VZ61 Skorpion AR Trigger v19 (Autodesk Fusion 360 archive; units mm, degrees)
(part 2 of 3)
extrude "Extrude35" cut sketch "Sketch22" profile of C1 against normal blind 9.398
extrude "Extrude36" cut of existing geometry blind 12
extrude "Extrude37" cut of existing geometry blind -88.9
extrude "Extrude38" add of existing geometry blind 0.0762 bodies "Body1", "Body2", "Body3", "Body4", "Body5"
chamfer "Chamfer2" distance 0.762
extrude "Extrude39" cut sketch "Sketch22" profile of C1 along normal blind 3
delete_face "DeleteFace1"
extrude "Extrude40" cut sketch "Sketch21" profile of L15 C2 L16 L17 L18 L19 L20 L21 L22 along normal blind 9.398
extrude "Extrude41" add of existing geometry blind 82.55
extrude "Extrude42" add of existing geometry blind 0.635
extrude "Extrude43" add of existing geometry blind 0.0254
external_derived "ExternalDerived2" bodies "Body5"
move "Move1"
move "Move2"
sketch "Sketch23" plane through (0, 65.024, 0) normal (0, -1, 0) x axis (1, 0, 0)
  line L1 (10.524, -2.2659) -> (15.9105, -2.2659)
  line L2 (17.4496, 2.7362) -> (14.383, 2.7362)
  line L3 (17.78, 3.81) -> (17.4496, 2.7362)
  line L4 (17.78, 10.16) -> (17.78, 3.81)
  line L5 (12.7, 25.4) -> (17.78, 10.16)
  line L6 (-12.7, 25.4) -> (12.7, 25.4)
  line L7 (-17.78, 10.16) -> (-12.7, 25.4)
  line L8 (-17.78, 3.81) -> (-17.78, 10.16)
  line L9 (-15.3535, -4.0762) -> (-17.78, 3.81)
  line L10 (-12.7, -12.7) -> (-15.3535, -4.0762)
  line L11 (-12.7, -12.6992) -> (-12.7, -12.7)
  line L12 (10.922, -12.6992) -> (-12.7, -12.6992)
  line L13 (10.922, -12.7) -> (10.922, -12.6992)
  line L14 (12.7, -12.7) -> (10.922, -12.7)
  line L15 (15.9105, -2.2659) -> (12.7, -12.7)
  line L16 (-1.2117, 23.5797) -> (-1.2117, 19.8432)
  line L17 (1.2883, 23.5797) -> (-1.2117, 23.5797)
  line L18 (1.2883, 19.8318) -> (1.2883, 23.5797)
  line L19 (14.3832, 25.3967) -> (19.4765, 10.1169)
  line L20 (17.3838, 25.3951) -> (22.4765, 10.1169)
  line L21 (17.3838, 25.3951) -> (14.3832, 25.3967)
  line L22 (0, 33.02) -> (0, 38.1)
  line L23 (-17.3838, 25.3951) -> (-22.4765, 10.1169)
  line L24 (-17.3838, 25.3951) -> (-14.3832, 25.3967)
  line L25 (-14.3832, 25.3967) -> (-19.4765, 10.1169)
  line L26 (-19.4765, 10.1169) -> (-22.4765, 10.1169)
  line L27 (22.4765, 10.1169) -> (19.4765, 10.1169)
  line L28 (-12.7, 25.4) -> (-14.3832, 25.3967)
  line L29 (-17.78, 10.16) -> (-19.4765, 10.1169)
  line L30 (14.3832, 25.3967) -> (12.7, 25.4)
  line L31 (19.4765, 10.1169) -> (17.78, 10.16)
  arc A1 centre (10, 2.128) radius 4.425 clockwise from (10.524, -2.2659) to (14.383, 2.7362)
  arc A2 centre (0, 11.43) radius 8.5 clockwise from (1.2883, 19.8318) to (-1.2117, 19.8432)
  circle C1 centre (0, 0) radius 2.75
  point P25 (19.4765, 10.1169)
  point P27 (19.4765, 10.1169)
  point P26 (22.4765, 10.1169)
  point P28 (22.4765, 10.1169)
  point P34 (-19.4765, 10.1169)
  point P37 (-22.4765, 10.1169)
  point P33 (-19.4765, 10.1169)
  point P35 (-22.4765, 10.1169)
  point P29 (17.3838, 25.3951)
  point P36 (-17.3838, 25.3951)
  point P30 (14.3832, 25.3967)
  point P38 (-14.3832, 25.3967)
  point P39 (-19.4765, 10.1169)
  point P40 (22.4765, 10.1169)
  point P10 (-12.7, 25.4)
  point P41 (-12.7, 25.4)
  point P42 (-19.4765, 10.1169)
  point P11 (-17.78, 10.16)
  point P43 (-17.78, 10.16)
  point P9 (12.7, 25.4)
  point P44 (12.7, 25.4)
  point P8 (17.78, 10.16)
  point P45 (17.78, 10.16)
  point P46 (19.4765, 10.1169)
  parallel L5 L19
  parallel L19 L20
  coincident P25 P27
  coincident P26 P28
  vertical L22
  symmetric P25 L22 P34
  symmetric P26 L22 P37
  symmetric P27 L22 P33
  symmetric P28 L22 P35
  symmetric P29 L22 P36
  symmetric P30 L22 P38
  coincident P33 P39
  coincident P28 P40
  coincident P10 P41
  coincident P33 P42
  coincident P11 P43
  coincident P9 P44
  coincident P8 P45
  coincident P27 P46
extrude "Extrude44" new body sketch "Sketch23" profile of L19 L20 L21 L23 L24 L25 L26 L27 along normal blind 24.6888
extrude "Extrude45" new body sketch "Sketch23" profile of L5 L7 L19 L20 L21 L23 L24 L25 L26 L27 L28 L29 L30 L31 against normal blind 6.35
sketch "Sketch24" plane through (9.4765, 0, 0) normal (1, 0, 0) x axis (0, 1, 0)
  line L1 (49.0432, -27.3325) -> (58.1554, -27.3325)
  line L2 (49.2242, -28.4751) -> (49.0432, -27.3325)
  line L3 (40.335, -29.8831) -> (49.2242, -28.4751)
  line L4 (41.1172, -34.8215) -> (40.335, -29.8831)
  line L5 (58.8956, -32.0057) -> (41.1172, -34.8215)
  line L6 (58.1554, -27.3325) -> (58.8956, -32.0057)
  line L7 (59.531, -23.368) -> (57.531, -23.368)
  line L8 (65.024, -10.16) -> (59.531, -23.368)
  line L9 (66.802, -12.7) -> (65.024, -10.16)
  line L10 (58.8956, -32.0057) -> (66.802, -12.7)
  line L11 (58.8956, -32.0057) -> (57.531, -23.368)
  point P7 (58.8956, -32.0057)
  point P12 (58.8956, -32.0057)
  point P8 (57.531, -23.368)
  point P9 (59.531, -23.368)
  horizontal L7
  coincident P7 P12
  dimension "d120" distance P8 P9 = 2
extrude "Extrude46" add sketch "Sketch24" profile of L7 L8 L9 L10 L11 against normal blind 18.9992 bodies "Body4", "Body1"
extrude "Extrude47" cut of existing geometry blind 31.75 second side blind 11.43
extrude "Extrude48" add of existing geometry blind 4.699 bodies "Body3"
extrude "Extrude49" add of existing geometry blind 13.0048
extrude "Extrude50" cut of existing geometry blind -7.62
delete_face "DeleteFace2"
delete_face "DeleteFace3"
delete_face "DeleteFace4"
extrude "Extrude51" cut of existing geometry blind -13.97
delete_face "DeleteFace5"
extrude "Extrude52" add of existing geometry blind 13.0048
delete_face "DeleteFace6"
extrude "Extrude53" cut of existing geometry blind -10.16
extrude "Extrude54" cut of existing geometry blind -8.89
delete_face "DeleteFace7"
delete_face "DeleteFace8"
extrude "Extrude55" add of existing geometry blind 0.01 (= "3.937E-04 in")
extrude "Extrude56" add of existing geometry blind 0.01 (= "3.937E-04 in")
extrude "Extrude57" add of existing geometry blind 6.35
extrude "Extrude58" add of existing geometry blind 6.35
sketch "Sketch25" plane through (-17.78, 0, 0) normal (-1, 0, 0) x axis (0, -1, 0)
  line L1 (-193.04, 3.81) -> (-193.04, 10.16)
  line L2 (-65.024, 3.81) -> (-193.04, 3.81)
  line L3 (-65.024, 10.16) -> (-65.024, 3.81)
  line L4 (-71.374, 10.16) -> (-65.024, 10.16)
  line L5 (-193.04, 10.16) -> (-71.374, 10.16)
  line L6 (-71.374, 10.16) -> (-65.024, 10.16)
  line L7 (-71.374, -10.16) -> (-71.374, 10.16)
  line L8 (-65.024, -10.16) -> (-71.374, -10.16)
  line L9 (-65.024, 10.16) -> (-65.024, -10.16)
  point P5 (-65.024, 10.16)
  point P7 (-65.024, 10.16)
  horizontal L6
  vertical L7
  horizontal L8
  vertical L9
  coincident P5 P7
extrude "Extrude59" add sketch "Sketch25" profile of L2 L3 L4 L6 L7 L8 L9 along normal blind 1.7526
delete_face "DeleteFace9"
extrude "Extrude60" add of existing geometry blind 13.97
extrude "Extrude61" add of existing geometry blind 0.01 (= "3.936E-04 in")
extrude "Extrude62" add of existing geometry blind 7.8994
extrude "Extrude63" add of existing geometry blind 1.524
sketch "Sketch26" plane through (17.78, 0, 0) normal (1, 0, 0) x axis (0, 1, 0)
  line L1 (193.04, 10.16) -> (193.04, 3.81)
  line L2 (153.924, 10.16) -> (193.04, 10.16)
  line L3 (71.374, 10.16) -> (153.924, 10.16)
  line L4 (65.024, 10.16) -> (71.374, 10.16)
  line L5 (65.024, 3.81) -> (65.024, 10.16)
  line L6 (193.04, 3.81) -> (65.024, 3.81)
  line L7 (71.384, 10.16) -> (65.024, 10.16)
  line L8 (71.384, 2.7362) -> (71.384, 10.16)
  line L9 (65.024, 2.7362) -> (71.384, 2.7362)
  line L10 (65.024, 10.16) -> (65.024, 2.7362)
  line L11 (71.384, -6.9688) -> (71.384, 10.1169)
  line L12 (146.3986, 2.7362) -> (65.024, 2.7362)
  line L13 (71.384, 10.1169) -> (65.024, 10.1217)
  point P6 (65.024, 10.16)
  point P8 (65.024, 10.16)
  point P17 (65.024, 10.1217)
  point P12 (71.384, 10.1169)
  point P18 (71.384, 10.1169)
  vertical L8
  horizontal L9
  vertical L10
  coincident P6 P8
  collinear L8 L11
  collinear L9 L12
  coincident L10 P17
  coincident P12 P18
extrude "Extrude64" add sketch "Sketch26" profile of L5 L6 L8 L9 L10 L11 L12 L13 along normal blind 4.699
extrude "Extrude65" add of existing geometry blind 0.01 (= "3.934E-04 in")
revolve "Revolve3" AlongAngle 10
delete_face "DeleteFace10"
delete_face "DeleteFace11"
extrude "Extrude66" add of existing geometry blind 2.286
extrude "Extrude67" add of existing geometry blind 2.286
extrude "Extrude68" cut of existing geometry blind -31.75
extrude "Extrude69" cut of existing geometry blind -5.0038
extrude "Extrude70" add of existing geometry blind 0.007 (= "2.745E-04 in")
extrude "Extrude71" cut of existing geometry blind -0.0053 (= "-2.080E-04 in")
extrude "Extrude72" add of existing geometry blind 0.001 (= "3.984E-05 in")
extrude "Extrude73" add of existing geometry blind 0.0015 (= "6.068E-05 in")
extrude "Extrude74" cut of existing geometry blind -0.0002 (= "-7.935E-06 in")
extrude "Extrude75" add of existing geometry blind 0.0009 (= "3.703E-05 in")
extrude "Extrude76" cut of existing geometry blind -0.0005 (= "-1.995E-05 in")
chamfer "Chamfer3" distance 4.572 rotateAngle 55
extrude "Extrude77" cut of existing geometry blind -0.0025 (= "-9.862E-05 in")
chamfer "Chamfer4" distance 5.334 rotateAngle 25
extrude "Extrude78" add of existing geometry blind 6.096
sketch "Sketch27" plane through (0, 65.024, 0) normal (0, -1, 0) x axis (1, 0, 0)
  line L1 (-1.2117, 23.5797) -> (-1.2117, 19.8432)
  line L2 (1.2883, 23.5797) -> (-1.2117, 23.5797)
  line L3 (1.2883, 19.8318) -> (1.2883, 23.5797)
  line L4 (15.947, -2.2659) -> (19.4765, -4.7373)
  line L5 (10.524, -2.2659) -> (15.947, -2.2659)
  line L6 (17.4496, 2.7362) -> (14.383, 2.7362)
  line L7 (17.78, 3.81) -> (17.4496, 2.7362)
  line L8 (19.4765, 3.81) -> (17.78, 3.81)
  line L9 (19.4765, 10.1169) -> (19.4765, 3.81)
  line L10 (14.3832, 25.3967) -> (19.4765, 10.1169)
  line L11 (14.3833, 25.3992) -> (14.3832, 25.3967)
  line L12 (12.7, 25.4025) -> (14.3833, 25.3992)
  line L13 (12.7, 31.496) -> (12.7, 25.4025)
  line L14 (-12.7, 31.496) -> (12.7, 31.496)
  line L15 (-12.7, 25.4003) -> (-12.7, 31.496)
  line L16 (-14.3833, 25.397) -> (-12.7, 25.4003)
  line L17 (-14.3832, 25.3967) -> (-14.3833, 25.397)
  line L18 (-19.4765, 10.1169) -> (-14.3832, 25.3967)
  line L19 (-19.5235, 10.1169) -> (-19.4765, 10.1169)
  line L20 (-19.5235, -6.8831) -> (-19.5235, 10.1169)
  line L21 (19.0531, -10.16) -> (-19.1001, -10.16)
  line L22 (19.4765, -4.7373) -> (19.4765, -6.8831)
  line L23 (-12.7, 25.4003) -> (-12.7, 31.496)
  line L24 (-12.7, 31.496) -> (-17.3838, 25.3951)
  line L25 (-12.7, 25.4003) -> (-17.3838, 25.3951)
  line L26 (12.7, 25.3954) -> (12.7, 31.496)
  line L27 (12.7, 31.496) -> (17.3838, 25.3951)
  line L28 (12.7, 25.3954) -> (17.3838, 25.3951)
  line L29 (-12.7, 27.636) -> (-14.3832, 25.3967)
  line L30 (0, 33.0007) -> (0, 36.8809)
  line L31 (12.7, 27.636) -> (14.3832, 25.3967)
  line L32 (12.7, 31.496) -> (-12.7, 31.496)
  line L33 (12.7, 25.3954) -> (12.7, 31.496)
  line L34 (-12.7, 25.3954) -> (12.7, 25.3954)
  line L35 (-12.7, 31.496) -> (-12.7, 25.3954)
  arc A1 centre (0, 11.43) radius 8.5 clockwise from (1.2883, 19.8318) to (-1.2117, 19.8432)
  circle C1 centre (0, 0) radius 2.75
  arc A2 centre (10, 2.128) radius 4.425 clockwise from (10.524, -2.2659) to (14.383, 2.7362)
  arc A3 centre (4.1935, -5.4847) radius 23.7582 clockwise from (-19.1001, -10.16) to (-19.5235, -6.8831)
  arc A4 centre (-4.2405, -5.4847) radius 23.7582 clockwise from (19.4765, -6.8831) to (19.0531, -10.16)
  point P22 (-12.7, 31.496)
  point P34 (-12.7, 31.496)
  point P23 (-12.7, 25.4003)
  point P35 (-12.7, 25.4003)
  point P37 (-12.7, 31.496)
  point P36 (-17.3838, 25.3951)
  point P38 (-17.3838, 25.3951)
  point P21 (12.7, 31.496)
  point P39 (12.7, 31.496)
  point P41 (17.3838, 25.3951)
  point P42 (17.3838, 25.3951)
  point P25 (-14.3832, 25.3967)
  point P43 (-14.3832, 25.3967)
  point P44 (-12.7, 27.636)
  point P47 (14.3832, 25.3967)
  point P48 (12.7, 27.636)
  coincident P22 P34
  coincident P23 P35
  coincident P22 P37
  coincident P36 P38
  coincident P21 P39
  coincident P41 P42
  coincident P25 P43
  coincident L23 P44
  perpendicular L14 L30
  symmetric P43 L30 P47
  symmetric P44 L30 P48
  horizontal L32
  vertical L33
  horizontal L34
  vertical L35
extrude "Extrude79" add sketch "Sketch27" profile of L10 L11 L12 L13 L15 L23 L24 L25 L26 L27 L28 L29 L31 along normal blind 24.6888
extrude "Extrude80" add sketch "Sketch27" profile of L10 L11 L12 L13 L15 L23 L24 L25 L26 L27 L28 L29 L31 against normal blind 6.35
extrude "Extrude81" add sketch "Sketch27" profile of L13 L14 L15 L23 L26 L32 L33 L34 L35 along normal blind 64.516
delete_face "DeleteFace12"
extrude "Extrude82" add sketch "Sketch27" profile of L12 L13 L15 L23 L25 L26 L29 L31 L33 L35 along normal blind 24.6888
sketch "Sketch28" plane through (0, 0, 31.496) normal (0, 0, 1) x axis (-1, 0, 0)
  line L1 (12.7, -193.04) -> (-12.7, -193.04)
  line L2 (12.7, -71.374) -> (12.7, -193.04)
  line L3 (12.7, -40.3352) -> (12.7, -71.374)
  line L4 (12.7, -0.508) -> (12.7, -40.3352)
  line L5 (-12.7, -0.508) -> (12.7, -0.508)
  line L6 (-12.7, -40.3352) -> (-12.7, -0.508)
  line L7 (-12.7, -71.374) -> (-12.7, -40.3352)
  line L8 (-12.7, -193.04) -> (-12.7, -71.374)
  line L9 (12.7, -40.3352) -> (17.3838, -40.3352)
  line L10 (12.7, -0.508) -> (17.3838, -40.3352)
  line L11 (0, 14.0534) -> (0, 5.08)
  line L12 (-12.7, -0.508) -> (-17.3838, -40.3352)
  line L13 (-12.7, -40.3352) -> (-17.3838, -40.3352)
  line L14 (-12.7, -0.508) -> (-12.7, -40.3352)
  point P11 (12.7, -40.3352)
  point P10 (17.3838, -40.3352)
  point P12 (17.3838, -40.3352)
  point P5 (12.7, -40.3352)
  point P6 (12.7, -0.508)
  point P13 (12.7, -0.508)
  point P19 (-12.7, -40.3352)
  point P20 (-12.7, -0.508)
  point P16 (-17.3838, -40.3352)
  point P18 (-12.7, -40.3352)
  point P17 (-12.7, -0.508)
  coincident L4 P11
  coincident P10 P12
  coincident P5 P11
  coincident P6 P13
  vertical L11
  symmetric P5 L11 P19
  symmetric P6 L11 P20
  symmetric P10 L11 P16
  symmetric P11 L11 P18
  symmetric P13 L11 P17
extrude "Extrude83" add sketch "Sketch28" profile of L4 L6 L9 L10 L12 L13 L14 against normal blind 6.096
extrude "Extrude84" cut of existing geometry blind -63.5
extrude "Extrude85" add of existing geometry blind 0.01 (= "3.935E-04 in")
extrude "Extrude86" add of existing geometry blind 6.35
extrude "Extrude87" add of existing geometry blind 0.01 (= "3.935E-04 in")
fillet "Fillet1" radius 1
fillet "Fillet2" radius 0.127
extrude "Extrude88" cut of existing geometry blind 0.0008 (= "2.992E-05 in")
extrude "Extrude89" cut of existing geometry blind -0.0008 (= "-2.994E-05 in")
sketch "Sketch29" plane through (0, 65.024, 0) normal (0, -1, 0) x axis (1, 0, 0)
  line L1 (12.7, 25.4025) -> (14.3833, 25.3992)
  line L2 (12.7, 25.3954) -> (12.7, 25.4025)
  line L3 (-12.7, 25.3954) -> (12.7, 25.3954)
  line L4 (-12.7, 25.4003) -> (-12.7, 25.3954)
  line L5 (-14.3833, 25.397) -> (-12.7, 25.4003)
  line L6 (-14.3832, 25.3967) -> (-14.3833, 25.397)
  line L7 (-19.4765, 10.1169) -> (-14.3832, 25.3967)
  line L8 (-19.5235, 10.1169) -> (-19.4765, 10.1169)
  line L9 (-19.5235, -6.8831) -> (-19.5235, 10.1169)
  line L10 (19.0531, -10.16) -> (-19.1001, -10.16)
  line L11 (19.4765, -4.7373) -> (19.4765, -6.8831)
  line L12 (15.947, -2.2659) -> (19.4765, -4.7373)
  line L13 (10.524, -2.2659) -> (15.947, -2.2659)
  line L14 (17.4496, 2.7362) -> (14.383, 2.7362)
  line L15 (17.78, 3.81) -> (17.4496, 2.7362)
  line L16 (19.4765, 3.81) -> (17.78, 3.81)
  line L17 (19.4765, 10.1169) -> (19.4765, 3.81)
  line L18 (14.3832, 25.3967) -> (19.4765, 10.1169)
  line L19 (14.3833, 25.3992) -> (14.3832, 25.3967)
  line L20 (-1.2117, 23.5797) -> (-1.2117, 19.8432)
  line L21 (1.2883, 23.5797) -> (-1.2117, 23.5797)
  line L22 (1.2883, 19.8318) -> (1.2883, 23.5797)
  line L23 (-9.5235, -28.4751) -> (9.4765, -28.4751)
  line L24 (-0.0235, -11.8564) -> (-0.0235, -8.4636)
  line L25 (-12.7, -12.7) -> (10.922, -12.7)
  line L26 (-6.2361, -23.4389) -> (-12.7, -12.7)
  line L27 (12.7002, -12.6992) -> (6.1903, -23.4331)
  line L28 (-12.7, -12.7) -> (12.7002, -12.6992)
  arc A1 centre (4.1935, -5.4847) radius 23.7582 clockwise from (-19.1001, -10.16) to (-19.5235, -6.8831)
  arc A2 centre (-4.2405, -5.4847) radius 23.7582 clockwise from (19.4765, -6.8831) to (19.0531, -10.16)
  arc A3 centre (10, 2.128) radius 4.425 clockwise from (10.524, -2.2659) to (14.383, 2.7362)
  circle C1 centre (0, 0) radius 2.75
  arc A4 centre (0, 11.43) radius 8.5 clockwise from (1.2883, 19.8318) to (-1.2117, 19.8432)
  circle C2 centre (-0.0235, -22.1251) radius 6.35
  point P33 (-0.0235, -22.1251)
  point P39 (-12.7, -12.7)
  point P40 (-12.7, -12.7)
  point P41 (-6.2361, -23.4389)
  point P42 (6.1903, -23.4331)
  point P43 (12.7002, -12.6992)
  point P44 (12.7002, -12.6992)
  point P45 (12.7002, -12.6992)
  point P46 (-12.7, -12.7)
  midpoint L10 L24
  coincident P33 L24
  perpendicular L10 L24
  tangent C2 L23
  coincident P39 P40
  coincident C2 P41
  coincident C2 P42
  coincident P43 P44
  coincident P44 P45
  coincident P39 P46
  dimension "d218" diameter C2 = 12.7
extrude "Extrude90" add sketch "Sketch29" profile of C2 L26 L27 L28 along normal blind 5.08 and against normal blind 6.35
delete_face "DeleteFace13"
work_plane "WorkPlane5" AlongDistance 4.2418
split_face "SplitFace1"
sketch "Sketch30" plane through (22.4765, 0, 0) normal (1, 0, 0) x axis (0, 1, 0)
  line L1 (59.69, -6.904) -> (71.384, -6.904)
  line L2 (59.69, 4.81) -> (59.69, -6.904)
  line L3 (71.384, 4.81) -> (59.69, 4.81)
  line L4 (71.384, 10.1169) -> (71.384, 4.81)
  line L5 (71.374, 10.1169) -> (71.384, 10.1169)
  line L6 (65.024, 10.1217) -> (71.374, 10.117)
  line L7 (65.024, 10.1169) -> (65.024, 10.1217)
  line L8 (40.3352, 10.1169) -> (65.024, 10.1169)
  line L9 (40.335, 10.1169) -> (40.3352, 10.1169)
  line L10 (40.335, -6.9688) -> (40.335, 10.1169)
  line L11 (71.384, -6.9688) -> (40.335, -6.9688)
  line L12 (71.384, -6.904) -> (71.384, -6.9688)
  line L13 (66.9901, -23.4331) -> (71.384, -12.6992)
  line L14 (71.384, -23.4331) -> (66.9901, -23.4331)
  line L15 (71.384, -12.6992) -> (71.384, -23.4331)
  line L16 (71.374, -23.4331) -> (66.9901, -23.4331)
  line L17 (64.4493, -29.6402) -> (66.9901, -23.4331)
  line L18 (71.374, -29.6402) -> (64.4493, -29.6402)
  line L19 (71.384, -23.4331) -> (71.374, -29.6402)
  point P16 (66.9901, -23.4331)
  point P18 (66.9901, -23.4331)
  point P15 (71.384, -12.6992)
  point P20 (71.384, -12.6992)
  perpendicular L14 L15
  coincident P16 P18
  coincident P15 P20
  parallel L13 L17
  perpendicular L15 L18
extrude "Extrude91" cut sketch "Sketch30" profile of L13 L14 L15 L16 L17 L18 L19 against normal blind 66.548
fillet "Fillet3" radius 6.985
chamfer "Chamfer5" distance 3.81 rotateAngle 75
chamfer "Chamfer6" distance 7.62 rotateAngle 45
chamfer "Chamfer7" distance 1.27 rotateAngle 60
delete_face "DeleteFace14"
extrude "Extrude92" add of existing geometry blind 0.254
extrude "Extrude93" cut of existing geometry blind -0.254
delete_face "DeleteFace15"
chamfer "Chamfer8" distance 3.81 rotateAngle 70
delete_face "DeleteFace16"
chamfer "Chamfer9" distance 2.54 rotateAngle 15
sketch "Sketch31" plane through (-17.78, 0, 0) normal (-1, 0, 0) x axis (0, -1, 0)
  line L1 (-71.384, 10.0059) -> (-71.384, 3.81)
  line L2 (-71.3089, 10.16) -> (-71.384, 10.0059)
  line L3 (-193.04, 10.16) -> (-71.3089, 10.16)
  line L4 (-193.04, 3.81) -> (-193.04, 10.16)
  line L5 (-71.384, 3.81) -> (-193.04, 3.81)
  line L6 (-40.3352, 25.3951) -> (-0.508, 25.4)
  line L7 (-40.335, 9.9759) -> (-40.3352, 25.3951)
  line L8 (-0.508, 25.4) -> (-40.335, 9.9759)
  point P7 (-0.508, 25.4)
  point P10 (-0.508, 25.4)
  point P8 (-40.3352, 25.3951)
  point P11 (-40.3352, 25.3951)
  point P9 (-40.335, 9.9759)
  point P12 (-40.335, 9.9759)
  coincident P7 P10
  coincident P8 P11
  coincident P9 P12
extrude "Extrude94" add sketch "Sketch31" profile of L6 L7 L8 along normal blind 24.13 and against normal blind 49.53
extrude "Extrude95" add of existing geometry blind 0.254
extrude "Extrude96" cut of existing geometry blind -71.12
delete_face "DeleteFace17"
extrude "Extrude97" cut of existing geometry blind -101.6
extrude "Extrude98" cut of existing geometry blind -86.36
delete_face "DeleteFace18"
sketch "Sketch32" plane through (0, 0.508, 0) normal (0, -1, 0) x axis (1, 0, 0)
  line L1 (12.7, 25.3956) -> (-12.7, 25.3956)
  line L2 (12.7, 25.4) -> (12.7, 25.3956)
  line L3 (12.7, 31.496) -> (12.7, 25.4)
  line L4 (-12.7, 31.496) -> (12.7, 31.496)
  line L5 (-12.7, 25.4) -> (-12.7, 31.496)
  line L6 (-12.7, 25.3956) -> (-12.7, 25.4)
  line L7 (-12.7, 25.4) -> (-12.7, 31.496)
  line L8 (-12.7, 31.496) -> (-17.3823, 25.4)
  line L9 (-12.7, 25.4) -> (-17.3823, 25.4)
  line L10 (0, 35.56) -> (0, 38.1)
  line L11 (12.7, 31.496) -> (17.3823, 25.4)
  line L12 (12.7, 25.4) -> (12.7, 31.496)
  line L13 (12.7, 25.4) -> (17.3823, 25.4)
  point P6 (-12.7, 31.496)
  point P8 (-12.7, 31.496)
  point P7 (-12.7, 25.4)
  point P9 (-12.7, 25.4)
  point P11 (-12.7, 31.496)
  point P10 (-17.3823, 25.4)
  point P12 (-17.3823, 25.4)
  point P17 (12.7, 31.496)
  point P18 (12.7, 25.4)
  point P15 (17.3823, 25.4)
  point P16 (12.7, 31.496)
  coincident P6 P8
  coincident P7 P9
  coincident P6 P11
  coincident P10 P12
  vertical L10
  symmetric P8 L10 P17
  symmetric P9 L10 P18
  symmetric P10 L10 P15
  symmetric P11 L10 P16
extrude "Extrude99" add sketch "Sketch32" profile of L3 L5 L7 L8 L9 L11 L12 L13 against normal blind 39.8272
chamfer "Chamfer10" distance 5.08
extrude "Extrude100" add of existing geometry blind 3.7592
extrude "Extrude101" cut of existing geometry blind -5
fillet "Fillet4" radius 3.81 3.81
fillet "Fillet5" radius 1.27
sketch "Sketch33" plane through (-22.5235, 0, 0) normal (-1, 0, 0) x axis (0, -1, 0)
  line L1 (-40.589, 9.9759) -> (-40.335, 9.9759)
  line L2 (-60.9161, 9.9759) -> (-40.589, 9.9759)
  line L3 (-60.9161, -6.9688) -> (-60.9161, 9.9759)
  line L4 (-40.335, -6.9688) -> (-60.9161, -6.9688)
  line L5 (-40.335, 9.9759) -> (-40.335, -6.9688)
  line L6 (-46.024, 19.812) -> (-65.024, 19.812)
  line L7 (-46.024, 9.812) -> (-46.024, 19.812)
  line L8 (-44.524, 9.812) -> (-44.524, 19.812)
  line L9 (-47.524, 9.812) -> (-47.524, 19.812)
  circle C1 centre (-46.024, 19.812) radius 1.5
  circle C2 centre (-46.024, 9.812) radius 1.5
  point P7 (-46.024, 19.812)
  point P9 (-46.024, 19.812)
  point P11 (-46.024, 19.812)
  point P10 (-46.024, 9.812)
  point P12 (-46.024, 9.812)
  point P13 (-44.524, 19.812)
  point P14 (-44.524, 9.812)
  point P15 (-47.524, 19.812)
  point P16 (-47.524, 9.812)
  point P8 (-65.024, 19.812)
  horizontal L6
  coincident P7 P9
  coincident P7 P11
  perpendicular L6 L7
  coincident P10 P12
  coincident C1 P13
  coincident C2 P14
  tangent C2 L8
  perpendicular L6 L8
  coincident C1 P15
  coincident L6 P15
  coincident C2 P16
  tangent C2 L9
  perpendicular L6 L9
  dimension "d263" diameter C1 = 3
  dimension "d264" distance P8 P9 = 19
  dimension "d265" diameter C2 = 3
  dimension "d266" distance P11 P12 = 10
extrude "Extrude102" cut sketch "Sketch33" profile of L2 C1 L6 C2 L7 L8 L9 against normal blind 92.71
delete_face "DeleteFace19"
delete_face "DeleteFace20"
fillet "Fillet6" radius 6.35
extrude "Extrude103" cut of existing geometry blind -22
delete_face "DeleteFace21"
delete_face "DeleteFace22"
delete_face "DeleteFace23"
sketch "Sketch34" plane through (0, 171.04, 0) normal (0, 1, 0) x axis (-1, 0, 0)
  line L1 (12.7, 25.4) -> (17.78, 10.16)
  line L2 (-6.3551, 31.496) -> (6.3551, 31.496)
  line L3 (-17.78, 10.16) -> (-12.7, 25.4)
  line L4 (-17.78, 3.81) -> (-17.78, 10.16)
  line L5 (-12.7, -12.7) -> (-17.78, 3.81)
  line L6 (-12.7, -12.6992) -> (-12.7, -12.7)
  line L7 (12.7, -12.6992) -> (-12.7, -12.6992)
  line L8 (12.7, -12.7) -> (12.7, -12.6992)
  line L9 (17.78, 3.81) -> (12.7, -12.7)
  line L10 (17.78, 10.16) -> (17.78, 3.81)
  line L11 (-1.2883, 24.8205) -> (-1.2883, 19.8318)
  line L12 (1.2117, 24.8205) -> (-1.2883, 24.8205)
  line L13 (1.2117, 19.8432) -> (1.2117, 24.8205)
  line L14 (-12.7, 3.81) -> (-15.24, 3.81)
  line L15 (-12.7, 10.1661) -> (-12.7, 3.81)
  line L16 (-17.78, 10.16) -> (-12.7, 10.1661)
  line L17 (-15.24, 3.81) -> (-17.78, 3.81)
  line L18 (-13.1655, 1.7355) -> (-15.24, 3.81)
  line L19 (-10.16, 3.81) -> (-15.24, 3.81)
  line L20 (-13.1655, 12.2375) -> (-15.24, 10.1631)
  line L21 (-10.16, 10.1631) -> (-15.24, 10.1631)
  line L22 (-11.6479, 2.3641) -> (-11.6479, 11.6089)
  line L23 (0.0387, 26.7371) -> (0.0387, 29.2871)
  line L24 (11.7254, 13.7552) -> (15.3175, 10.1631)
  line L25 (11.7254, 0.2179) -> (11.7254, 13.7552)
  line L26 (11.7254, 0.2179) -> (15.3175, 3.81)
  line L27 (12.7775, 10.1661) -> (12.7775, 3.81)
  line L28 (17.8575, 10.16) -> (12.7775, 10.1661)
  line L29 (15.3175, 3.81) -> (17.8575, 3.81)
  line L30 (12.7775, 3.81) -> (15.3175, 3.81)
  line L31 (11.7254, 2.3641) -> (11.7254, 11.6089)
  line L32 (13.243, 12.2376) -> (15.3175, 10.1631)
  line L33 (13.243, 1.7355) -> (15.3175, 3.81)
  arc A1 centre (6.3551, 25.146) radius 6.35 clockwise from (6.3551, 31.496) to (12.7, 25.4)
  arc A2 centre (-6.3551, 25.146) radius 6.35 clockwise from (-12.7, 25.4) to (-6.3551, 31.496)
  arc A3 centre (0, 11.43) radius 8.5 clockwise from (1.2117, 19.8432) to (-1.2883, 19.8318)
  arc A4 centre (-12.5369, 11.6089) radius 0.889 clockwise from (-13.1655, 12.2375) to (-11.6479, 11.6089)
  arc A5 centre (-12.5369, 2.3641) radius 0.889 clockwise from (-11.6479, 2.3641) to (-13.1655, 1.7355)
  arc A6 centre (12.6144, 11.6089) radius 0.889 clockwise from (11.7254, 11.6089) to (13.243, 12.2376)
  arc A7 centre (12.6144, 2.3641) radius 0.889 clockwise from (13.243, 1.7355) to (11.7254, 2.3641)
  point P11 (-17.78, 10.16)
  point P26 (-17.78, 10.16)
  point P12 (-17.78, 3.81)
  point P27 (-17.78, 3.81)
  point P30 (-15.24, 10.1631)
  point P23 (-15.24, 3.81)
  point P38 (15.3175, 3.81)
  point P24 (-12.7, 3.81)
  point P39 (12.7775, 3.81)
  point P25 (-12.7, 10.1661)
  point P40 (12.7775, 10.1661)
  point P41 (17.8575, 10.16)
  point P42 (17.8575, 3.81)
  point P28 (-11.6479, 0.2179)
  point P37 (11.7254, 0.2179)
  point P31 (-11.6479, 13.7552)
  point P36 (11.7254, 13.7552)
  point P55 (15.3175, 3.81)
  point P54 (15.3175, 10.1631)
  point P43 (-13.1655, 12.2375)
  point P53 (13.243, 12.2376)
  point P44 (-11.6479, 11.6089)
  point P51 (11.7254, 11.6089)
  point P46 (-13.1655, 1.7355)
  point P56 (13.243, 1.7355)
  point P47 (-11.6479, 2.3641)
  point P52 (11.7254, 2.3641)
  perpendicular L4 L14
  perpendicular L14 L15
  coincident P11 P26
  coincident P12 P27
  horizontal L17
  horizontal L19
  horizontal L21
  midpoint L16 P30
  parallel L22 L23
  symmetric P23 L23 P38
  symmetric P24 L23 P39
  symmetric P25 L23 P40
  symmetric P26 L23 P41
  symmetric P27 L23 P42
  symmetric P28 L23 P37
  symmetric P31 L23 P36
  coincident P31 L20
  coincident P31 L22
  tangent L20 A4
  tangent L22 A4
  coincident P28 L18
  coincident P28 L22
  tangent L18 A5
  tangent L22 A5
  equal A4 A5
  symmetric P23 L23 P55
  symmetric P30 L23 P54
  symmetric L23 P43 P53
  symmetric L23 P44 P51
  symmetric L23 A4 A6
  symmetric L23 P46 P56
  symmetric L23 P47 P52
  symmetric L23 A5 A7
  dimension "d272" distance P23 P24 = 2.54
  dimension "d273" angle L18 L19 = 45
  dimension "d274" distance P23 P28 = 5.08
  dimension "d275" angle L20 L21 = 45
  dimension "d276" distance P30 P31 = 5.08
  dimension "d277" radius A4 = 0.889
extrude "Extrude104" cut sketch "Sketch34" profile of L1 L4 L10 L14 L15 L16 L17 L18 L20 L22 L24 L25 L26 L27 L28 L29 L30 A4 A5 L31 A6 L32 L33 A7 against normal blind 12.7
sketch "Sketch35" plane through (0, 171.04, 0) normal (0, 1, 0) x axis (-1, 0, 0)
  line L1 (-1.2883, 24.8205) -> (-1.2883, 19.8318)
  line L2 (1.2117, 24.8205) -> (-1.2883, 24.8205)
  line L3 (1.2117, 19.8432) -> (1.2117, 24.8205)
  line L4 (-15.24, 10.1631) -> (-17.78, 10.16)
  line L5 (-13.1655, 12.2375) -> (-15.24, 10.1631)
  line L6 (-11.6479, 2.3641) -> (-11.6479, 11.6089)
  line L7 (-15.24, 3.81) -> (-13.1655, 1.7355)
  line L8 (-17.78, 3.81) -> (-15.24, 3.81)
  line L9 (-12.7, -12.7) -> (-17.78, 3.81)
  line L10 (-12.7, -12.6992) -> (-12.7, -12.7)
  line L11 (12.7, -12.6992) -> (-12.7, -12.6992)
  line L12 (12.7, -12.7) -> (12.7, -12.6992)
  line L13 (17.78, 3.81) -> (12.7, -12.7)
  line L14 (15.3175, 3.81) -> (17.78, 3.81)
  line L15 (13.243, 1.7355) -> (15.3175, 3.81)
  line L16 (11.7254, 11.6089) -> (11.7254, 2.3641)
  line L17 (15.3175, 10.1631) -> (13.243, 12.2376)
  line L18 (17.78, 10.1601) -> (15.3175, 10.1631)
  line L19 (12.7, 25.4) -> (17.78, 10.1601)
  line L20 (-6.3551, 31.496) -> (6.3551, 31.496)
  line L21 (-17.78, 10.16) -> (-12.7, 25.4)
  line L22 (7.8359, 31.496) -> (-7.8359, 31.496)
  line L23 (7.8359, 40.8178) -> (7.8359, 31.496)
  line L24 (-7.8359, 40.8178) -> (7.8359, 40.8178)
  line L25 (-7.8359, 31.496) -> (-7.8359, 40.8178)
  line L26 (10.6045, 40.8178) -> (-10.6045, 40.8178)
  line L27 (10.6045, 35.0394) -> (10.6045, 40.8178)
  line L28 (-10.6045, 34.9781) -> (10.6045, 35.0394)
  line L29 (-10.6045, 40.8178) -> (-10.6045, 34.9781)
  line L30 (10.6045, 40.8178) -> (-10.6045, 40.8178)
  line L31 (10.6045, 36.6522) -> (10.6045, 40.8178)
  line L32 (-10.6045, 36.6522) -> (10.6045, 36.6522)
  line L33 (-10.6045, 40.8178) -> (-10.6045, 36.6522)
  line L34 (-10.6045, 37.8979) -> (-7.8359, 40.8178)
  line L35 (-7.8359, 34.9861) -> (-10.6045, 37.8979)
  line L36 (10.6045, 37.9286) -> (7.8359, 40.8178)
  line L37 (10.6045, 37.9286) -> (7.8359, 35.0314)
  arc A1 centre (0, 11.43) radius 8.5 clockwise from (1.2117, 19.8432) to (-1.2883, 19.8318)
  arc A2 centre (-12.5369, 11.6089) radius 0.889 clockwise from (-13.1655, 12.2375) to (-11.6479, 11.6089)
  arc A3 centre (-12.5369, 2.3641) radius 0.889 clockwise from (-11.6479, 2.3641) to (-13.1655, 1.7355)
  arc A4 centre (12.6144, 2.3641) radius 0.889 clockwise from (13.243, 1.7355) to (11.7254, 2.3641)
  arc A5 centre (12.6144, 11.6089) radius 0.889 clockwise from (11.7254, 11.6089) to (13.243, 12.2376)
  arc A6 centre (6.3551, 25.146) radius 6.35 clockwise from (6.3551, 31.496) to (12.7, 25.4)
  arc A7 centre (-6.3551, 25.146) radius 6.35 clockwise from (-12.7, 25.4) to (-6.3551, 31.496)
  point P48 (10.6045, 36.6522)
  point P50 (-10.6045, 37.8979)
  point P51 (-7.8359, 34.9861)
  point P52 (10.6045, 37.9286)
  point P53 (7.8359, 35.0314)
  point P39 (-7.8359, 31.496)
  point P40 (7.8359, 31.496)
  point P42 (-7.8359, 40.8178)
  point P43 (-10.6045, 40.8178)
  point P44 (10.6045, 40.8178)
  point P49 (-10.6045, 36.6522)
  horizontal L22
  vertical L23
  midpoint L24 L26
  vertical L31
  vertical L33
  coincident L27 P48
  collinear L29 L33
  midpoint L29 P50
  coincident L28 P51
  coincident L25 P51
  midpoint L27 P52
  coincident L23 P53
  coincident L28 P53
  midpoint L20 L22
  dimension "d280" distance P39 P40 = 15.6718
  dimension "d281" distance P39 P42 = 9.3218
  dimension "d283" distance P43 P44 = 21.209
  dimension "d284" distance P43 P49 = 4.1656
extrude "Extrude105" new body sketch "Sketch35" profile of L20 L22 L23 L24 L25 L26 L28 L30 L32 L34 L35 L36 L37 against normal blind 166.37
extrude "Extrude106" cut of existing geometry blind -0.9144
sketch "Sketch36" plane through (7.8359, 0, 0) normal (1, 0, 0) x axis (0, 1, 0)
  line L1 (5.5844, 31.496) -> (5.5844, 34.9861)
  line L2 (171.04, 31.496) -> (5.5844, 31.496)
  line L3 (171.04, 34.9861) -> (171.04, 31.496)
  line L4 (5.5844, 34.9861) -> (171.04, 34.9861)
  line L5 (171.04, 40.8178) -> (165.8076, 40.8178)
  line L6 (171.04, 37.8979) -> (171.04, 40.8178)
  line L7 (165.8076, 37.8979) -> (171.04, 37.8979)
  line L8 (5.5844, 37.8979) -> (5.5844, 40.8178)
  line L9 (165.8076, 40.8178) -> (160.5752, 40.8178)
  line L10 (160.5752, 37.8979) -> (165.8076, 37.8979)
  line L11 (165.8076, 37.8979) -> (165.8076, 40.8178)
  line L12 (160.5752, 40.8178) -> (155.3428, 40.8178)
  line L13 (155.3428, 37.8979) -> (160.5752, 37.8979)
  line L14 (160.5752, 37.8979) -> (160.5752, 40.8178)
  line L15 (155.3428, 40.8178) -> (150.1104, 40.8178)
  line L16 (150.1104, 37.8979) -> (155.3428, 37.8979)
  line L17 (155.3428, 37.8979) -> (155.3428, 40.8178)
  line L18 (150.1104, 40.8178) -> (144.878, 40.8178)
  line L19 (144.878, 37.8979) -> (150.1104, 37.8979)
  line L20 (150.1104, 37.8979) -> (150.1104, 40.8178)
  line L21 (144.878, 40.8178) -> (139.6456, 40.8178)
  line L22 (139.6456, 37.8979) -> (144.878, 37.8979)
  line L23 (144.878, 37.8979) -> (144.878, 40.8178)
  line L24 (139.6456, 40.8178) -> (134.4132, 40.8178)
  line L25 (134.4132, 37.8979) -> (139.6456, 37.8979)
  line L26 (139.6456, 37.8979) -> (139.6456, 40.8178)
  line L27 (134.4132, 40.8178) -> (129.1808, 40.8178)
  line L28 (129.1808, 37.8979) -> (134.4132, 37.8979)
  line L29 (134.4132, 37.8979) -> (134.4132, 40.8178)
  line L30 (129.1808, 40.8178) -> (123.9484, 40.8178)
  line L31 (123.9484, 37.8979) -> (129.1808, 37.8979)
  line L32 (129.1808, 37.8979) -> (129.1808, 40.8178)
  line L33 (123.9484, 40.8178) -> (118.716, 40.8178)
  line L34 (118.716, 37.8979) -> (123.9484, 37.8979)
  line L35 (123.9484, 37.8979) -> (123.9484, 40.8178)
  line L36 (118.716, 40.8178) -> (113.4836, 40.8178)
  line L37 (113.4836, 37.8979) -> (118.716, 37.8979)
  line L38 (118.716, 37.8979) -> (118.716, 40.8178)
  line L39 (113.4836, 40.8178) -> (108.2512, 40.8178)
  line L40 (108.2512, 37.8979) -> (113.4836, 37.8979)
  line L41 (113.4836, 37.8979) -> (113.4836, 40.8178)
  line L42 (108.2512, 40.8178) -> (103.0188, 40.8178)
  line L43 (103.0188, 37.8979) -> (108.2512, 37.8979)
  line L44 (108.2512, 37.8979) -> (108.2512, 40.8178)
  line L45 (103.0188, 40.8178) -> (97.7864, 40.8178)
  line L46 (97.7864, 37.8979) -> (103.0188, 37.8979)
  line L47 (103.0188, 37.8979) -> (103.0188, 40.8178)
  line L48 (97.7864, 40.8178) -> (92.554, 40.8178)
  line L49 (92.554, 37.8979) -> (97.7864, 37.8979)
  line L50 (97.7864, 37.8979) -> (97.7864, 40.8178)
  line L51 (92.554, 40.8178) -> (87.3216, 40.8178)
  line L52 (87.3216, 37.8979) -> (92.554, 37.8979)
  line L53 (92.554, 37.8979) -> (92.554, 40.8178)
  line L54 (87.3216, 40.8178) -> (82.0892, 40.8178)
  line L55 (82.0892, 37.8979) -> (87.3216, 37.8979)
  line L56 (87.3216, 37.8979) -> (87.3216, 40.8178)
  line L57 (82.0892, 40.8178) -> (76.8568, 40.8178)
  line L58 (76.8568, 37.8979) -> (82.0892, 37.8979)
  line L59 (82.0892, 37.8979) -> (82.0892, 40.8178)
  line L60 (76.8568, 40.8178) -> (71.6244, 40.8178)
  line L61 (71.6244, 37.8979) -> (76.8568, 37.8979)
  line L62 (76.8568, 37.8979) -> (76.8568, 40.8178)
  line L63 (71.6244, 40.8178) -> (66.392, 40.8178)
  line L64 (66.392, 37.8979) -> (71.6244, 37.8979)
  line L65 (71.6244, 37.8979) -> (71.6244, 40.8178)
  line L66 (165.8076, 37.8979) -> (165.8076, 40.8178)
  line L67 (160.5752, 37.8979) -> (160.5752, 40.8178)
  line L68 (155.3428, 37.8979) -> (155.3428, 40.8178)
  line L69 (150.1104, 37.8979) -> (150.1104, 40.8178)
  line L70 (144.878, 37.8979) -> (144.878, 40.8178)
  line L71 (139.6456, 37.8979) -> (139.6456, 40.8178)
  line L72 (134.4132, 37.8979) -> (134.4132, 40.8178)
  line L73 (129.1808, 37.8979) -> (129.1808, 40.8178)
  line L74 (123.9484, 37.8979) -> (123.9484, 40.8178)
  line L75 (118.716, 37.8979) -> (118.716, 40.8178)
  line L76 (113.4836, 37.8979) -> (113.4836, 40.8178)
  line L77 (108.2512, 37.8979) -> (108.2512, 40.8178)
  line L78 (103.0188, 37.8979) -> (103.0188, 40.8178)
  line L79 (97.7864, 37.8979) -> (97.7864, 40.8178)
  line L80 (92.554, 37.8979) -> (92.554, 40.8178)
  line L81 (87.3216, 37.8979) -> (87.3216, 40.8178)
  line L82 (82.0892, 37.8979) -> (82.0892, 40.8178)
  line L83 (76.8568, 37.8979) -> (76.8568, 40.8178)
  line L84 (71.6244, 37.8979) -> (71.6244, 40.8178)
  line L85 (66.392, 37.8979) -> (66.392, 40.8178)
  line L86 (66.392, 40.8178) -> (61.1596, 40.8178)
  line L87 (61.1596, 37.8979) -> (66.392, 37.8979)
  line L88 (66.392, 37.8979) -> (66.392, 40.8178)
  line L89 (61.1596, 37.8979) -> (61.1596, 40.8178)
  line L90 (61.1596, 40.8178) -> (55.9272, 40.8178)
  line L91 (55.9272, 37.8979) -> (61.1596, 37.8979)
  line L92 (61.1596, 37.8979) -> (61.1596, 40.8178)
  line L93 (55.9272, 37.8979) -> (55.9272, 40.8178)
  line L94 (55.9272, 40.8178) -> (50.6948, 40.8178)
  line L95 (50.6948, 37.8979) -> (55.9272, 37.8979)
  line L96 (55.9272, 37.8979) -> (55.9272, 40.8178)
  line L97 (50.6948, 37.8979) -> (50.6948, 40.8178)
  line L98 (50.6948, 40.8178) -> (45.4624, 40.8178)
  line L99 (45.4624, 37.8979) -> (50.6948, 37.8979)
  line L100 (50.6948, 37.8979) -> (50.6948, 40.8178)
  line L101 (45.4624, 37.8979) -> (45.4624, 40.8178)
  line L102 (45.4624, 40.8178) -> (40.23, 40.8178)
  line L103 (40.23, 37.8979) -> (45.4624, 37.8979)
  line L104 (45.4624, 37.8979) -> (45.4624, 40.8178)
  line L105 (40.23, 37.8979) -> (40.23, 40.8178)
  line L106 (40.23, 40.8178) -> (34.9976, 40.8178)
  line L107 (34.9976, 37.8979) -> (40.23, 37.8979)
  line L108 (40.23, 37.8979) -> (40.23, 40.8178)
  line L109 (34.9976, 37.8979) -> (34.9976, 40.8178)
  line L110 (34.9976, 40.8178) -> (29.7652, 40.8178)
  line L111 (29.7652, 37.8979) -> (34.9976, 37.8979)
  line L112 (34.9976, 37.8979) -> (34.9976, 40.8178)
  line L113 (29.7652, 37.8979) -> (29.7652, 40.8178)
  line L114 (29.7652, 40.8178) -> (24.5328, 40.8178)
  line L115 (24.5328, 37.8979) -> (29.7652, 37.8979)
  line L116 (29.7652, 37.8979) -> (29.7652, 40.8178)
  line L117 (24.5328, 37.8979) -> (24.5328, 40.8178)
  line L118 (24.5328, 40.8178) -> (19.3004, 40.8178)
  line L119 (19.3004, 37.8979) -> (24.5328, 37.8979)
  line L120 (24.5328, 37.8979) -> (24.5328, 40.8178)
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  point P7 (171.04, 40.8178)
  point P8 (171.04, 37.8979)
  point P6 (165.8076, 40.8178)
  horizontal L5
  vertical L6
  horizontal L7
  collinear L3 L6
  perpendicular L7 L66
  dimension "d294" distance P7 P8 = 2.9199
  dimension "d295" distance P6 P7 = 5.2324
  dimension "d298" R-Pattern1-uDistance = -5.2324
  dimension "d299" R-Pattern1-vDistance = 0
extrude "Extrude107" cut sketch "Sketch36" profile of L9 L10 L11 L14 L15 L16 L17 L20 L21 L22 L23 L26 L27 L28 L29 L32 L33 L34 L35 L38 L39 L40 L41 L44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 against normal blind 22.86 and along normal blind 7.62
copy_paste_bodies "CopyPasteBodies1"
move "Move3"
extrude "Extrude108" cut of existing geometry blind -66.04
sketch "Sketch37" plane through (0, 71.6244, 0) normal (0, -1, 0) x axis (1, 0, 0)
  line L1 (-8.0899, -22.0218) -> (-10.8585, -19.1019)
  line L2 (7.5819, -22.0218) -> (-8.0899, -22.0218)
  line L3 (10.3505, -19.1326) -> (7.5819, -22.0218)
  line L4 (7.5819, -16.2354) -> (10.3505, -19.1326)
  line L5 (7.5819, -12.7) -> (7.5819, -16.2354)
  line L6 (-8.0899, -12.7) -> (7.5819, -12.7)
  line L7 (-8.0899, -16.1901) -> (-8.0899, -12.7)
  line L8 (-10.8585, -19.1019) -> (-8.0899, -16.1901)
  line L9 (7.5819, -12.7) -> (-8.0899, -12.7)
  line L10 (7.5819, -16.2354) -> (7.5819, -12.7)
  line L11 (-8.0899, -16.2354) -> (7.5819, -16.2354)
  line L12 (-8.0899, -12.7) -> (-8.0899, -16.2354)
  point P6 (7.5819, -16.2354)
  point P12 (7.5819, -16.2354)
  point P8 (-8.0899, -12.7)
  point P10 (-8.0899, -12.7)
  horizontal L9
  vertical L10
  horizontal L11
  vertical L12
  coincident P6 P12
  coincident P8 P10
extrude "Extrude109" new body sketch "Sketch37" profile of L5 L6 L7 L9 L10 L11 L12 along normal blind 3.302
extrude "Extrude110" new body of existing geometry blind 12.7
extrude "Extrude111" new body of existing geometry blind 25.4
combine "Combine1"
chamfer "Chamfer11" distance 10.16
extrude "Extrude112" cut of existing geometry distance -33.02
fillet "Fillet7" radius 2.54 2.54
sketch "Sketch38" plane through (17.78, 0, 0) normal (1, 0, 0) x axis (0, 1, 0)
  line L1 (181.2, 10.16) -> (181.2, 3.81)
  line L2 (171.04, 10.16) -> (181.2, 10.16)
  line L3 (158.34, 10.16) -> (171.04, 10.16)
  line L4 (158.34, 3.81) -> (158.34, 10.16)
  line L5 (171.04, 3.81) -> (158.34, 3.81)
  line L6 (181.2, 3.81) -> (171.04, 3.81)
  line L7 (176.1398, 2.276) -> (176.1398, 21.326)
  line L8 (174.6398, 2.2761) -> (174.6404, 21.3659)
  line L9 (177.6398, 2.2761) -> (177.6393, 21.3659)
  circle C1 centre (176.1398, 21.326) radius 1.5
  circle C2 centre (176.1398, 2.276) radius 1.5
  point P8 (176.1398, 21.326)
  point P9 (176.1398, 21.326)
  point P10 (176.1398, 2.276)
  point P11 (176.1398, 2.276)
  point P12 (174.6404, 21.3659)
  point P13 (174.6398, 2.2761)
  point P14 (177.6393, 21.3659)
  point P15 (177.6398, 2.2761)
  coincident P8 P9
  perpendicular L6 L7
  coincident P10 P11
  coincident C1 P12
  coincident C2 P13
  tangent C2 L8
  coincident C1 P14
  coincident C2 P15
  tangent C2 L9
  dimension "d317" diameter C1 = 3
  dimension "d318" distance P9 P10 = 19.05
  dimension "d319" diameter C2 = 3
extrude "Extrude113" cut sketch "Sketch38" profile of L2 L6 C1 L7 C2 L8 L9 against normal blind 53.34
extrude "Extrude114" new body of existing geometry blind 3.556
combine "Combine2"
delete_face "DeleteFace25"
delete_face "DeleteFace26"
chamfer "Chamfer13" distance 2.54
chamfer "Chamfer14" distance 1.778
chamfer "Chamfer15" distance 1.016
sketch "Sketch39" plane through (-22.5235, 0, 0) normal (-1, 0, 0) x axis (0, -1, 0)
  line L1 (-47.524, 9.9759) -> (-47.515, 9.9759)
  line L2 (-60.9161, 9.9759) -> (-47.524, 9.9759)
  line L3 (-60.9161, -6.9688) -> (-60.9161, 9.9759)
  line L4 (-40.335, -6.9688) -> (-60.9161, -6.9688)
  line L5 (-40.335, 9.9759) -> (-40.335, -6.9688)
  line L6 (-40.589, 9.9759) -> (-40.335, 9.9759)
  line L7 (-44.524, 9.9759) -> (-40.589, 9.9759)
  line L8 (-44.533, 9.9759) -> (-44.524, 9.9759)
  line L9 (-62.024, -2.2659) -> (-146.3986, -2.2659)
  arc A1 centre (-46.024, 9.812) radius 1.5 clockwise from (-44.533, 9.9759) to (-47.515, 9.9759)
  circle C1 centre (-53.1056, -4.2344) radius 2.6035
  dimension "d328" diameter C1 = 5.207
  dimension "d329" distance L3 C1 = 5.207
  dimension "d330" distance C1 L9 = 0.635
extrude "Extrude115" cut sketch "Sketch39" profile of C1 against normal blind 10.16
chamfer "Chamfer16" distance 2.54
sketch "Sketch40" plane through (-22.5235, 0, 0) normal (-1, 0, 0) x axis (0, -1, 0)
  line L1 (-40.335, -6.9688) -> (-48.7492, -6.9688)
  line L2 (-40.335, 9.9759) -> (-40.335, -6.9688)
  line L3 (-40.589, 9.9759) -> (-40.335, 9.9759)
  line L4 (-44.524, 9.9759) -> (-40.589, 9.9759)
  line L5 (-44.533, 9.9759) -> (-44.524, 9.9759)
  line L6 (-47.524, 9.9759) -> (-47.515, 9.9759)
  line L7 (-60.9161, 9.9759) -> (-47.524, 9.9759)
  line L8 (-60.9161, -6.9688) -> (-60.9161, 9.9759)
  line L9 (-57.4621, -6.9688) -> (-60.9161, -6.9688)
  line L10 (-0.508, 26.416) -> (-5.588, 31.496)
  line L11 (-40.335, 9.9759) -> (-0.508, 25.4)
  line L12 (-0.508, 25.4) -> (-0.508, 26.416)
  arc A1 centre (-53.1056, -4.2344) radius 5.1435 clockwise from (-57.4621, -6.9688) to (-48.7492, -6.9688)
  arc A2 centre (-46.024, 9.812) radius 1.5 clockwise from (-44.533, 9.9759) to (-47.515, 9.9759)
  circle C1 centre (-2.052, 26.164) radius 1.27
  point P17 (-0.508, 26.416)
  point P20 (-0.508, 26.416)
  point P18 (-0.508, 25.4)
  point P21 (-0.508, 25.4)
  tangent C1 L10
  tangent C1 L11
  coincident P17 P20
  coincident P18 P21
  dimension "d334" diameter C1 = 2.54
extrude "Extrude116" cut sketch "Sketch40" profile of C1 L10 L11 L12 against normal blind 68.58 bodies "Body2 (1) (1)"
chamfer "Chamfer17" distance 1.016
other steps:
derived_base_feature "Derived Base Feature1" bodies "Body1", "Body2", "Body3"
derived_base_feature "Derived Base Feature2" bodies "Body1", "Body3", "Body4", "Body5"
base_feature "Base Feature"
named bodies: "Body1", "Body2", "Body3", "Body4", "Body5", "Body2 (1)", "Body2 (1) (3)", "Body2 (1) (1)"

design "KN20 Base" references "HRR PRA Base"
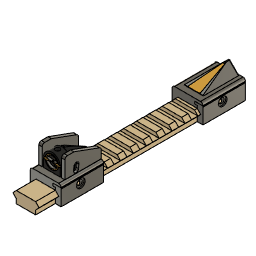
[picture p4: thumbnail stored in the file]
external_derived "ExternalDerived" bodies "Picatinny Base"
sketch "Base" plane through (0, 5.5844, 0) normal (0, -1, 0) x axis (1, 0, 0)
  line L1 (7.8359, 40.8178) -> (10.6045, 37.8979)
  line L2 (-7.8359, 40.8178) -> (7.8359, 40.8178)
  line L3 (-10.6045, 37.9286) -> (-7.8359, 40.8178)
  line L4 (-7.8359, 35.0314) -> (-10.6045, 37.9286)
  line L5 (-7.8359, 31.496) -> (-7.8359, 35.0314)
  line L6 (7.8359, 31.496) -> (-7.8359, 31.496)
  line L7 (7.8359, 34.9861) -> (7.8359, 31.496)
  line L8 (10.6045, 37.8979) -> (7.8359, 34.9861)
  line L9 (12.5, 31.496) -> (-12.5, 31.496)
  line L10 (-12.5, 44) -> (-12.5, 31.496)
  line L11 (12.5, 32) -> (12.5, 31.496)
  line L12 (12.5, 44) -> (12.5, 32)
  line L13 (-12.5, 44) -> (12.5, 44)
  line L14 (7.8359, 44) -> (7.8359, 40.8178)
  point P3 (7.8359, 40.8178)
  point P15 (7.8359, 40.8178)
  point P16 (7.8359, 44)
  point P10 (-12.5, 31.496)
  point P11 (12.5, 31.496)
  point P13 (12.5, 32)
  point P14 (12.5, 44)
  midpoint L6 L9
  horizontal L9
  perpendicular L9 L10
  perpendicular L9 L11
  perpendicular L9 L12
  perpendicular L10 L13
  coincident P3 P15
  coincident L13 P16
  perpendicular L13 L14
  dimension "d1" distance P10 P11 = 25
  dimension "d2" distance P13 P14 = 12
extrude "Extrude1" new body sketch "Base" profile of L2 L3 L4 L5 L9 L10 L13 L14 against normal blind 29.413
extrude "Extrude2" new body sketch "Base" profile of L1 L7 L8 L9 L11 L12 L13 L14 against normal blind 29.413
sketch "Sketch2" plane through (0, 0, 44) normal (0, 0, 1) x axis (-1, 0, 0)
  line L1 (-7.8359, -5.5844) -> (12.5, -5.5844)
  line L2 (-7.8359, -34.9974) -> (-7.8359, -5.5844)
  line L3 (12.5, -34.9974) -> (-7.8359, -34.9974)
  line L4 (12.5, -5.5844) -> (12.5, -34.9974)
  line L5 (10.6045, -5.5844) -> (10.6045, -34.9974)
  line L6 (10.6045, -34.9974) -> (10.6045, -5.5844)
  line L7 (-10.6045, -5.5844) -> (-10.6045, -34.9974)
  line L8 (-10.6045, -34.9974) -> (-10.6045, -5.5844)
  line L9 (-7.8359, -34.9974) -> (-10.6045, -34.9974)
  line L10 (-7.8359, -5.5844) -> (-10.6045, -5.5844)
  line L11 (7.8359, -5.5844) -> (7.8359, -34.9974)
  line L12 (7.8359, -34.9974) -> (7.8359, -5.5844)
  point P6 (10.6045, -34.9974)
  point P7 (10.6045, -5.5844)
  point P11 (-10.6045, -5.5844)
  point P12 (-10.6045, -5.5844)
  point P10 (-10.6045, -34.9974)
  point P13 (-10.6045, -34.9974)
  point P14 (-10.6045, -34.9974)
  point P4 (-7.8359, -34.9974)
  point P15 (-7.8359, -34.9974)
  point P3 (-7.8359, -5.5844)
  point P16 (-7.8359, -5.5844)
  point P17 (7.8359, -34.9974)
  point P18 (7.8359, -5.5844)
  coincident L3 P6
  coincident L1 P7
  perpendicular L1 L5
  collinear L5 L6
  parallel L2 L7
  collinear L7 L8
  coincident P11 P12
  coincident P10 P13
  coincident P13 P14
  coincident P4 P15
  coincident P3 P16
  coincident L3 P17
  coincident L1 P18
  perpendicular L1 L11
  collinear L11 L12
extrude "Extrude3" new body sketch "Sketch2" profile of L1 L2 L3 L5 L6 L7 L8 L9 L10 L11 L12 along normal blind 13 bodies "Rear Sight Base"
sketch "Sketch3" plane through (0, 5.5844, 0) normal (0, -1, 0) x axis (1, 0, 0)
  line L1 (12.5, 31.496) -> (7.8359, 31.496)
  line L2 (12.5, 44) -> (12.5, 31.496)
  line L3 (7.8359, 44) -> (12.5, 44)
  line L4 (7.8359, 40.8178) -> (7.8359, 44)
  line L5 (10.6045, 37.8979) -> (7.8359, 40.8178)
  line L6 (7.8359, 34.9861) -> (10.6045, 37.8979)
  line L7 (7.8359, 31.496) -> (7.8359, 34.9861)
  line L8 (6.8359, 56.75) -> (-6.8359, 56.75)
  line L9 (6.8359, 45) -> (6.8359, 56.75)
  line L10 (-6.8359, 45) -> (6.8359, 45)
  line L11 (-6.8359, 56.75) -> (-6.8359, 45)
  line L12 (-12.5, 44) -> (12.5, 44)
  line L13 (-6.8359, 44) -> (-6.8359, 45)
  line L14 (6.8359, 44) -> (6.8359, 45)
  line L15 (-5.4872, 50.875) -> (-6.8359, 50.875)
  line L16 (5.4872, 50.875) -> (6.8359, 50.875)
  line L17 (-7.8359, 57) -> (-10.6045, 57)
  circle C1 centre (0, 51.25) radius 5.5
  circle C2 centre (0, 51.25) radius 4.5
  point P20 (6.8359, 44)
  point P21 (-6.8359, 50.875)
  point P22 (-5.4872, 50.875)
  point P23 (6.8359, 50.875)
  point P24 (5.4872, 50.875)
  horizontal L8
  vertical L9
  horizontal L10
  vertical L11
  concentric C1 C2
  vertical L13
  coincident L12 P20
  perpendicular L10 L14
  midpoint L11 P21
  coincident C1 P22
  perpendicular L11 L15
  midpoint L9 P23
  coincident C1 P24
  perpendicular L9 L16
  tangent L8 C1
  dimension "d10" distance L4 L9 = 1
  dimension "d11" distance L10 L12 = 1
  dimension "d13" distance L8 L17 = 0.25
extrude "Extrude4" new body sketch "Sketch3" profile of L9 L10 L11 L12 C1 C2 L13 L14 L15 L16 against normal blind 15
